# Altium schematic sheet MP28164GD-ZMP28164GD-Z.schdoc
size 127 x 101 mm
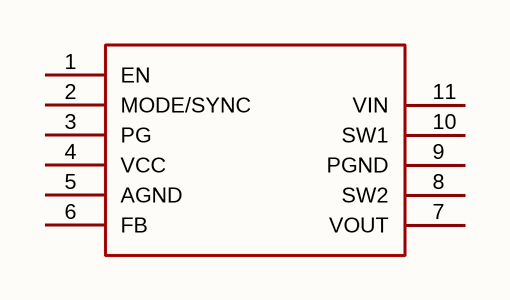
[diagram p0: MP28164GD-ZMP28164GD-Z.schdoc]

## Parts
U?  mp28164gd-z  [QFN-11_L3.0-W2.0-P0.50-BL]  (value not drawn)

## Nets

Not connected (* = marked no-connect by the designer): U? 1(EN) 2(MODE/SYNC) 3(PG) 4(VCC) 5(AGND) 6(FB) 7(VOUT) 8(SW2) 9(PGND) 10(SW1) 11(VIN)

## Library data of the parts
U? = mp28164gd-z: 功能类型:升降压型;工作电压:1.2V~5.5V;输出电压:1.5V~5V;输出电流:2A;输出类型:可调;; Manufacturer: MPS(芯源); AddInBom: yes; ModelId: 048308bed35047f590c3c9301ba09a0d; ModelTransform: 79.527,118.11,0,90,0,0,0,0,0; Function: 升降压型; Output Current: 2A; Frequency - Switching: 2MHz; Synchronous Rectifier: 是; Number of Outputs: 1; Topology: 降压-升压式; Quiescent Current: 25uA; Switch tube (built-in/external): 内置; Output Type: 可调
